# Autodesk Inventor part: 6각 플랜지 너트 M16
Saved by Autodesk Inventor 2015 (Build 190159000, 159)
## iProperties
Created: 2026-07
Part Number: 6각 플랜지 너트 M16
Material: 일반
Document SubType Name: Modeling
Designer: USER
Density: 1 g/cm^3
Appearance: 기본값
Author: USER
Author: jhkim
Creation Date: 2026-07-01
Sending System: Autodesk Inventor 2027
Preprocessor: ST-DEVELOPER v20.1
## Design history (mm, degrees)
node "6각 플랜지 너트 M161"
body "Solid1"
node "기준1"
